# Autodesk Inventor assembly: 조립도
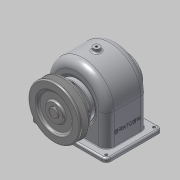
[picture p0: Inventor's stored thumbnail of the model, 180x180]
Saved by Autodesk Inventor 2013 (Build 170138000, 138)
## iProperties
Created: 2016-01
Part Number: 조립도
Document SubType Name: Assembly
Designer: dgall
Author: dgall
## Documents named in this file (16)
- C:\Users\dgall\Desktop\461015V1008.dwg\조립도.iam
- C:\Users\dgall\Desktop\461015V1008.dwg\본체.ipt
- C:\Users\dgall\Desktop\461015V1008.dwg\공용부품\V-벨트풀리.ipt
- C:\Users\dgall\Desktop\461015V1008.dwg\공용부품\뒤커버.ipt
- C:\Users\dgall\Desktop\461015V1008.dwg\공용부품\멈춤나사 - M4x10.ipt
- C:\Users\dgall\Desktop\461015V1008.dwg\공용부품\베어링 6203.ipt
- C:\Users\dgall\Desktop\461015V1008.dwg\공용부품\볼트 M3 x 8.ipt
- C:\Users\dgall\Desktop\461015V1008.dwg\공용부품\볼트 M3 x 10.ipt
- C:\Users\dgall\Desktop\461015V1008.dwg\공용부품\부시1.ipt
- C:\Users\dgall\Desktop\461015V1008.dwg\공용부품\부시2.ipt
- C:\Users\dgall\Desktop\461015V1008.dwg\공용부품\스퍼기어.ipt
- C:\Users\dgall\Desktop\461015V1008.dwg\공용부품\앞커버.ipt
- C:\Users\dgall\Desktop\461015V1008.dwg\공용부품\오일씰 28 40 8.ipt
- C:\Users\dgall\Desktop\461015V1008.dwg\공용부품\축.ipt
- C:\Users\dgall\Desktop\461015V1008.dwg\공용부품\키 - 5 x 5 x 18.ipt
- C:\Users\dgall\Desktop\461015V1008.dwg\공용부품\키 - 6 x 6 x 22.ipt
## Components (9 placed, 3 different names)
1. V-벨트풀리:1 — 플러쉬:1
2. ISO 4762 M3 x 8:1
3. ISO 4762 M3 x 10:1
4. ISO 4762 M3 x 10:2
5. ISO 4762 M3 x 10:3
6. ISO 4762 M3 x 10:4
7. ISO 4762 M3 x 8:2
8. ISO 4762 M3 x 8:3
9. ISO 4762 M3 x 8:4
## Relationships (1: Flush 1)
- 플러쉬:1 [Flush]: V-벨트풀리:1
